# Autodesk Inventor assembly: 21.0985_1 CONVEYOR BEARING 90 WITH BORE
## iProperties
Created: 2007-07
Part Number: 21.0985_1 CONVEYOR BEARING 90 WITH BORE
Document SubType Name: Assembly
Designer: Andy Moles
Author: Andy Moles
